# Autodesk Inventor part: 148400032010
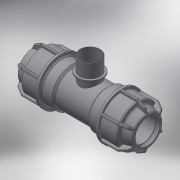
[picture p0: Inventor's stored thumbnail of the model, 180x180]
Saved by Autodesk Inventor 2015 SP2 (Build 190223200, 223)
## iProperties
Created: 2017-08
Part Number: 148400032010
Material: Generic
Description: PLASSON L.14 TEE MALE ADAPTOR (SILVER) 32-1"-32
Document SubType Name: Modeling
Designer: KIM
Density: 1 g/cm^3
Appearance: Default
Author: KIM
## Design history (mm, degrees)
derived "148400.ipt"
feature "Solid1::148400.ipt"
feature "Solid2::148400.ipt"
tag "TaggingFeature1"
body "Solid1"
body "Solid2"
other parameters: "d1" = 32, "d2" = 56, "d4" = 15 deg, "d5" = 36.96, "d6" = 12.1968, "d10" = 61, "d16" = 32.64, "d17" = 2.8, "d22" = 51.2, "d24" = 2.8, "d25" = 54.9, "d26" = 45.75, "d27" = 2.8, "d28" = 135 deg, "d29" = 1.68, "d31" = 1.6, "d46" = 150 deg, "d49" = 3.05, "d50" = 0, "d58" = 0.96, "d61" = 360 deg, "d63" = 28.8, "d64" = 75, "d80" = 46.08, "d81" = 2.56, "d84" = 2.8, "d94" = 53, "d96" = 33.249, "d108" = 0.96, "d111" = 0, "d113" = 25.6, "d114" = 39.8988, "d116" = 2, "d117" = 33.249, "d_" = 32, "R_" = 33.249, "E_" = 61, "l_" = 56, "A_" = 53
